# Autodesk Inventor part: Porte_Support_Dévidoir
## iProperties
Created: 2009-01
Part Number: Porte_Support_Dévidoir
Document SubType Name: Modeling
Designer: claivier
Author: claivier
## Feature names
1. Extrusion1
2. Perçage1 [Hole]
3. Perçage2 [Hole]
